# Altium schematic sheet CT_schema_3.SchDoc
size 365 x 192 mm
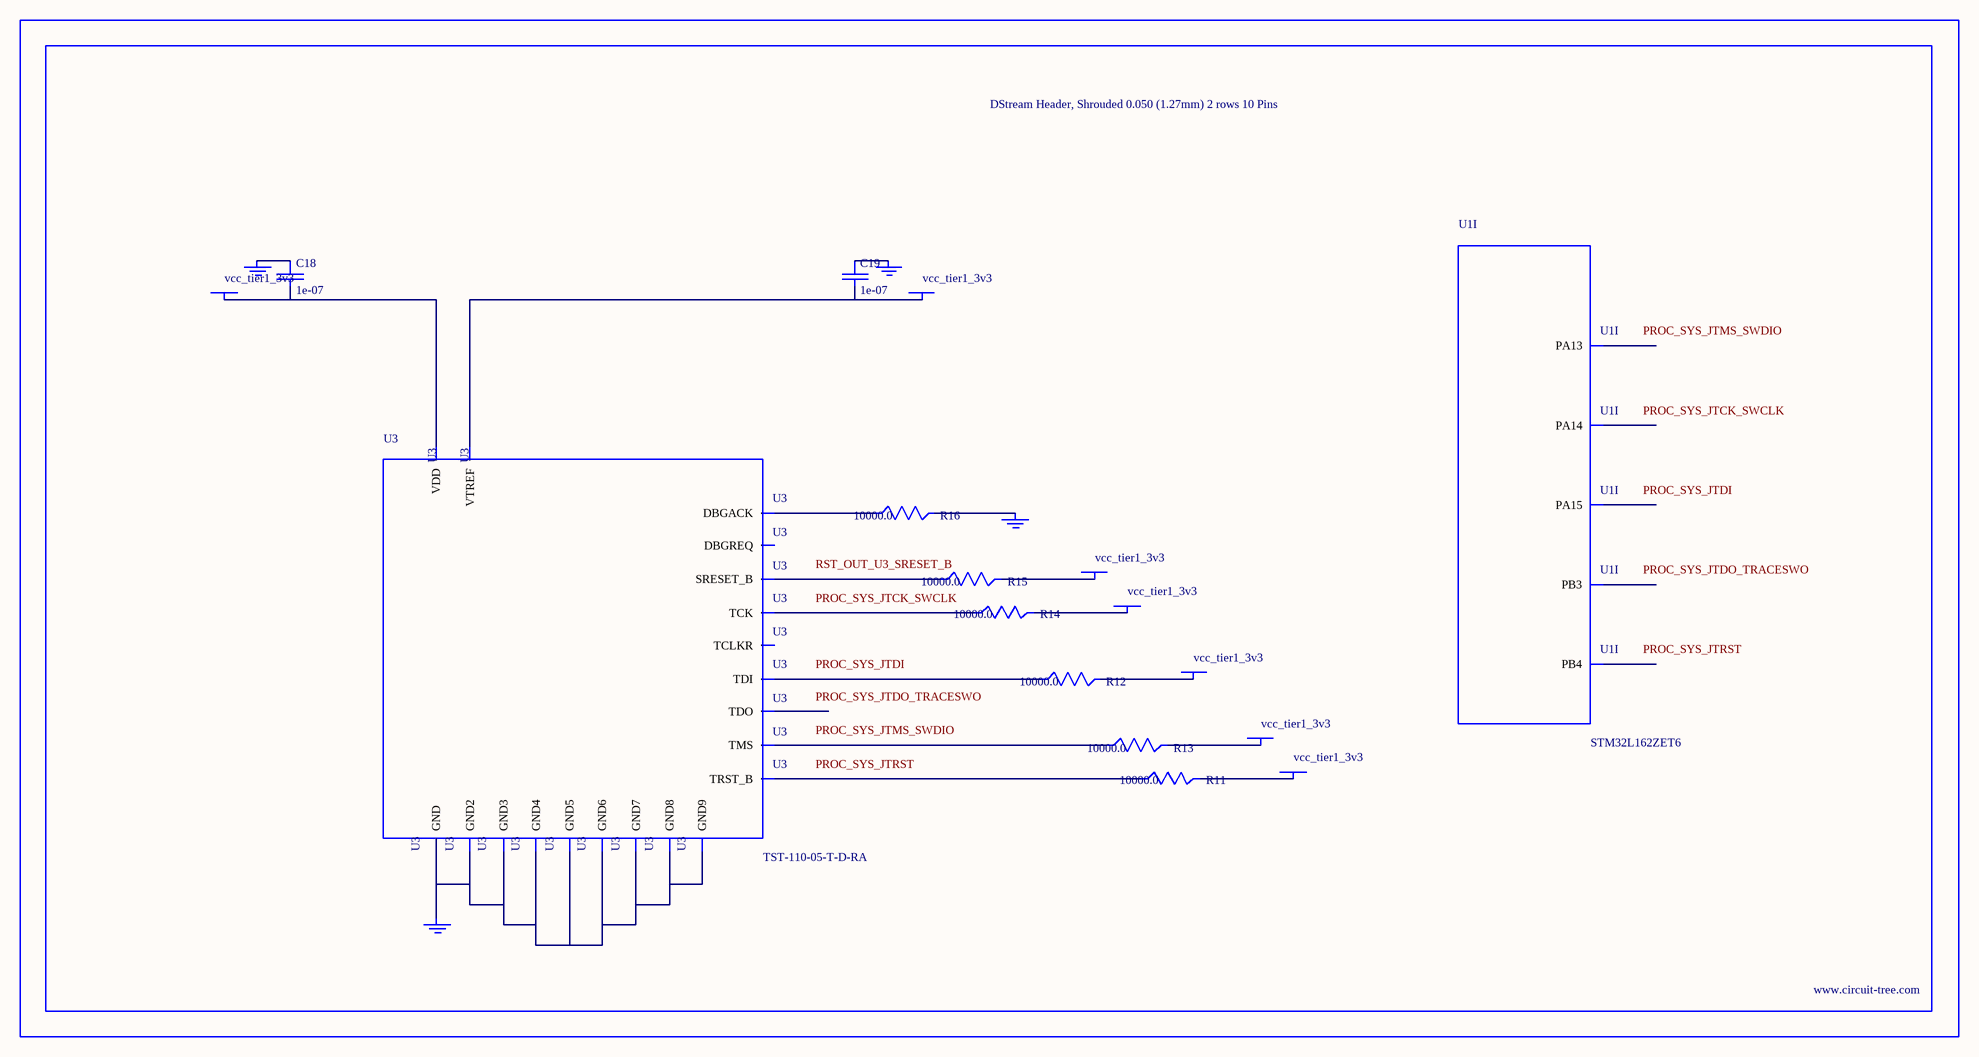
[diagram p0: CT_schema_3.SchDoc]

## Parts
BORDER2  (no value)
C18  1e-07  [C0402]
C19  1e-07  [C0402]
GND_INSTANCE_2_0  (no value)
GND_INSTANCE_2_1  (no value)
GND_INSTANCE_2_2  (no value)
GND_INSTANCE_2_3  (no value)
POWER_INSTANCE_2_0  vcc_tier1_3v3
POWER_INSTANCE_2_1  vcc_tier1_3v3
POWER_INSTANCE_2_2  vcc_tier1_3v3
POWER_INSTANCE_2_3  vcc_tier1_3v3
POWER_INSTANCE_2_4  vcc_tier1_3v3
POWER_INSTANCE_2_5  vcc_tier1_3v3
POWER_INSTANCE_2_6  vcc_tier1_3v3
R11  10000.0  [R0603]
R12  10000.0  [R0603]
R13  10000.0  [R0603]
R14  10000.0  [R0603]
R15  10000.0  [R0603]
R16  10000.0  [R0603]
U1  STM32L162ZET6  [LQFP144]  (part I of 13)
U3  TST-110-05-T-D-RA  [TST-110-05-T-D-RA]

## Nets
NetC18_1: C18.1 GND_INSTANCE_2_1.0(GND)
NetC18_2: C18.2 POWER_INSTANCE_2_1.0(PWR) U3.2(VDD)
NetC19_1: C19.1 GND_INSTANCE_2_0.0(GND)
NetC19_2: C19.2 POWER_INSTANCE_2_0.0(PWR) U3.1(VTREF)
NetGND_INSTANCE_2_2_0: GND_INSTANCE_2_2.0(GND) R16.2
NetGND_INSTANCE_2_3_0: GND_INSTANCE_2_3.0(GND) U3.4(GND) U3.6(GND2) U3.8(GND3) U3.10(GND4) U3.12(GND5) U3.14(GND6) U3.16(GND7) U3.18(GND8) U3.20(GND9)
NetPOWER_INSTANCE_2_2_0: POWER_INSTANCE_2_2.0(PWR) R11.2
NetPOWER_INSTANCE_2_3_0: POWER_INSTANCE_2_3.0(PWR) R12.2
NetPOWER_INSTANCE_2_4_0: POWER_INSTANCE_2_4.0(PWR) R13.2
NetPOWER_INSTANCE_2_5_0: POWER_INSTANCE_2_5.0(PWR) R14.2
NetPOWER_INSTANCE_2_6_0: POWER_INSTANCE_2_6.0(PWR) R15.2
NetR11_1: R11.1 U3.3(TRST_B)
NetR12_1: R12.1 U3.5(TDI)
NetR13_1: R13.1 U3.7(TMS)
NetR14_1: R14.1 U3.9(TCK)
NetR15_1: R15.1 U3.15(SRESET_B)
NetR16_1: R16.1 U3.19(DBGACK)

Not connected (* = marked no-connect by the designer): U1 105(PA13) 109(PA14) 110(PA15) 133(PB3) 134(PB4); U3 11(TCLKR) 13(TDO) 17(DBGREQ)

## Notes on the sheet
- Labels drawn without touching a wire or pin: PROC_SYS_JTCK_SWCLK, PROC_SYS_JTDI, PROC_SYS_JTDO_TRACESWO, PROC_SYS_JTMS_SWDIO, PROC_SYS_JTRST, RST_OUT_U3_SRESET_B

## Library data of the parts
BORDER2 = BORDER_PAGE2
C18 C19 = C0402C104K3RACTU
GND_INSTANCE_2_0-GND_INSTANCE_2_3 = GND
POWER_INSTANCE_2_0-POWER_INSTANCE_2_6 = PWR
R11-R16 = RC0603JR-0710KL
